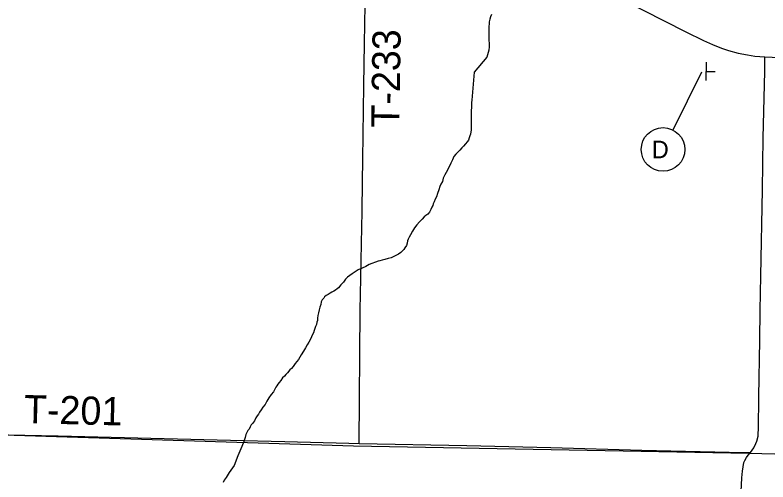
# Model space of a CAD drawing. Extents: x 1 to 1971, y -2 to 1107.
# Drawn here: x 1657.44 to 1664.12, y 1091.98 to 1096.12 of the extents above; entities that cross this region are included whole.
import ezdxf

# ---------------------------------------------------------------- set-up
doc = ezdxf.new("R2010")
doc.units = 0
for name, color, linetype in [('GM_X_County_Road', 7, 'Continuous'), ('GM_X_Minor_River', 7, 'Continuous'), ('GM_X_State_Route', 7, 'Continuous'), ('GM_X_Township', 7, 'Continuous'), ('GM_X_Township_Road', 7, 'Continuous'), ('GM_X_Township_Road_Text', 7, 'Continuous'), ('SH_Text', 7, 'Continuous'), ('SN_P_Signs', 7, 'Continuous')]:
    doc.layers.add(name, color=color, linetype=linetype)

msp = doc.modelspace()

# ---------------------------------------------------------------- linework, layer by layer
at = {"layer": 'GM_X_County_Road'}
for points in [[(1663.9663, 1092.2384), (1663.9964, 1092.279), (1664.0163, 1092.3184), (1664.0244, 1092.3391), (1664.0345, 1092.3822), (1664.037, 1092.4043), (1664.0399, 1092.4484), (1664.0401, 1092.7334), (1664.0507, 1093.2364), (1664.0534, 1093.499), (1664.0583, 1093.8051), (1664.0729, 1094.5707), (1664.0814, 1095.0301), (1664.0961, 1095.6206), (1664.0956, 1095.7086), (1664.0954, 1095.7491)], [(1663.9663, 1092.2384), (1663.9964, 1092.279), (1664.0163, 1092.3184), (1664.0244, 1092.3391), (1664.0345, 1092.3822), (1664.037, 1092.4043), (1664.0399, 1092.4484), (1664.0401, 1092.7334), (1664.0507, 1093.2364), (1664.0534, 1093.499), (1664.0583, 1093.8051), (1664.0729, 1094.5707), (1664.0814, 1095.0301), (1664.0961, 1095.6206), (1664.0956, 1095.7086), (1664.0954, 1095.7491)], [(1663.7714, 1088.7638), (1663.7757, 1088.9203), (1663.7916, 1089.4012), (1663.8088, 1089.904), (1663.8208, 1090.2091), (1663.8384, 1090.5818), (1663.8499, 1090.9095), (1663.8728, 1091.5685), (1663.885, 1091.8932), (1663.8919, 1092.014), (1663.8966, 1092.0716), (1663.9012, 1092.1103), (1663.9093, 1092.1486), (1663.9186, 1092.1687), (1663.9325, 1092.1954), (1663.9457, 1092.2144), (1663.9663, 1092.2384)], [(1663.7714, 1088.7638), (1663.7757, 1088.9203), (1663.7916, 1089.4012), (1663.8088, 1089.904), (1663.8208, 1090.2091), (1663.8384, 1090.5818), (1663.8499, 1090.9095), (1663.8728, 1091.5685), (1663.885, 1091.8932), (1663.8919, 1092.014), (1663.8966, 1092.0716), (1663.9012, 1092.1103), (1663.9093, 1092.1486), (1663.9186, 1092.1687), (1663.9325, 1092.1954), (1663.9457, 1092.2144), (1663.9663, 1092.2384)]]:
    msp.add_lwpolyline(points, dxfattribs=at)
at = {"layer": 'GM_X_Minor_River'}
for points in [[(1661.666, 1096.1256), (1661.6577, 1096.1043), (1661.652, 1096.083), (1661.6464, 1096.0616), (1661.6461, 1096.0402), (1661.6432, 1096.0215), (1661.6429, 1096.0001), (1661.6426, 1095.9759), (1661.6423, 1095.9518), (1661.6448, 1095.9304), (1661.6444, 1095.9009), (1661.6466, 1095.8661), (1661.6463, 1095.8393), (1661.6432, 1095.8099), (1661.6376, 1095.7885), (1661.6319, 1095.7671), (1661.6263, 1095.7458), (1661.5131, 1095.613)], [(1661.5131, 1095.613), (1661.4928, 1095.3669), (1661.4901, 1095.3455), (1661.49, 1095.3241), (1661.49, 1095.3027), (1661.4872, 1095.2706), (1661.4872, 1095.2465), (1661.4871, 1095.2144), (1661.487, 1095.1876), (1661.487, 1095.1635), (1661.4869, 1095.1421), (1661.4869, 1095.1207), (1661.4869, 1095.0993), (1661.4841, 1095.0833), (1661.4814, 1095.0646), (1661.476, 1095.0485), (1661.4706, 1095.0298), (1661.4626, 1095.0111), (1661.4518, 1094.9951), (1661.4357, 1094.9791), (1661.4196, 1094.9577), (1661.4035, 1094.9417), (1661.3848, 1094.9231), (1661.366, 1094.9017), (1661.3499, 1094.8857), (1661.3338, 1094.8644), (1661.3203, 1094.835), (1661.3069, 1094.8056), (1661.2961, 1094.7842), (1661.2639, 1094.7228), (1661.2531, 1094.7041), (1661.2397, 1094.6747), (1661.2316, 1094.6426), (1661.2182, 1094.6213), (1661.2101, 1094.5999), (1661.1993, 1094.5705), (1661.1885, 1094.5384), (1661.1778, 1094.509), (1661.167, 1094.4877), (1661.1589, 1094.4636), (1661.1482, 1094.4449), (1661.1455, 1094.4315), (1661.1374, 1094.4155), (1661.1293, 1094.3941), (1661.1159, 1094.3728), (1661.1025, 1094.3541), (1661.0837, 1094.3408), (1661.0703, 1094.3301), (1661.0516, 1094.3088), (1661.0274, 1094.2848), (1661.0033, 1094.2581), (1660.9845, 1094.2314), (1660.9657, 1094.202), (1660.9496, 1094.17), (1660.9361, 1094.1486), (1660.9281, 1094.1326), (1660.9227, 1094.1166), (1660.92, 1094.0978), (1660.9119, 1094.0765), (1660.8985, 1094.0551), (1660.8877, 1094.0391), (1660.8636, 1094.0124), (1660.8421, 1093.9991), (1660.8234, 1093.9884), (1660.7993, 1093.9778), (1660.7752, 1093.9672), (1660.7484, 1093.9593), (1660.7216, 1093.9513), (1660.6975, 1093.946), (1660.6761, 1093.9407), (1660.66, 1093.9355), (1660.5797, 1093.9063), (1660.5502, 1093.8903), (1660.5181, 1093.8744), (1660.4833, 1093.8584), (1660.4565, 1093.8425), (1660.4297, 1093.8238), (1660.4082, 1093.8105), (1660.3895, 1093.7945), (1660.3707, 1093.7759), (1660.3519, 1093.7492), (1660.3304, 1093.7251), (1660.309, 1093.7011), (1660.2956, 1093.6905), (1660.2822, 1093.6798), (1660.2661, 1093.6692), (1660.25, 1093.6612), (1660.2339, 1093.6532), (1660.2179, 1093.6399), (1660.1991, 1093.6319), (1660.1857, 1093.6213), (1660.1777, 1093.6079), (1660.1642, 1093.5946), (1660.1562, 1093.5759), (1660.1508, 1093.5518), (1660.1427, 1093.5278)], [(1660.1427, 1093.5278), (1660.1373, 1093.5037), (1660.1319, 1093.477), (1660.1265, 1093.4529), (1660.1237, 1093.4315), (1660.121, 1093.4101), (1660.1156, 1093.3941), (1660.1129, 1093.3753), (1660.1048, 1093.3566), (1660.0994, 1093.3379), (1660.094, 1093.3219), (1660.086, 1093.3005), (1660.0752, 1093.2791), (1660.0618, 1093.2498), (1660.0456, 1093.2177), (1660.0295, 1093.1937), (1660.0161, 1093.167), (1659.9973, 1093.1376), (1659.9785, 1093.1055), (1659.9543, 1093.0628), (1659.9248, 1093.0281), (1659.906, 1093.0014), (1659.8899, 1092.9828), (1659.8765, 1092.9721), (1659.855, 1092.9454), (1659.8416, 1092.9294), (1659.8282, 1092.9161), (1659.8121, 1092.9001), (1659.796, 1092.8787), (1659.7826, 1092.86), (1659.7692, 1092.844), (1659.7611, 1092.8307), (1659.7531, 1092.8173), (1659.7423, 1092.8013), (1659.7316, 1092.7773), (1659.7101, 1092.7532), (1659.6913, 1092.7239), (1659.6725, 1092.6945), (1659.6564, 1092.6651), (1659.6376, 1092.6411), (1659.6215, 1092.6171), (1659.6081, 1092.5957), (1659.5973, 1092.5797), (1659.5866, 1092.5637), (1659.5758, 1092.545), (1659.5624, 1092.5209), (1659.5436, 1092.4969), (1659.5329, 1092.4836), (1659.5248, 1092.4676), (1659.5141, 1092.4462), (1659.5033, 1092.4328), (1659.4953, 1092.4168), (1659.4872, 1092.3981), (1659.4791, 1092.3714), (1659.4656, 1092.3286), (1659.4414, 1092.2698), (1659.4145, 1092.2084), (1659.3822, 1092.1229), (1659.3366, 1092.0615), (1659.3124, 1092.0161), (1659.2936, 1091.9921), (1659.2855, 1091.9707)]]:
    msp.add_lwpolyline(points, dxfattribs=at)
at = {"layer": 'GM_X_State_Route'}
msp.add_lwpolyline([(1662.8274, 1096.2607), (1663.3928, 1095.972), (1663.5499, 1095.8949), (1663.6295, 1095.859), (1663.7106, 1095.8271), (1663.7726, 1095.8067), (1663.8567, 1095.7839), (1663.9422, 1095.767), (1664.0068, 1095.7573), (1664.0954, 1095.7491), (1664.3558, 1095.737)], dxfattribs=at)
at = {"layer": 'GM_X_Township'}
msp.add_lwpolyline([(1653.1763, 1092.4976), (1656.8592, 1092.4086), (1656.9549, 1092.4071), (1660.4424, 1092.2976), (1663.9517, 1092.2334), (1668.658, 1092.1116), (1671.0761, 1092.0354), (1672.2022, 1091.993)], dxfattribs=at)
at = {"layer": 'GM_X_Township_Road'}
for points in [[(1660.4916, 1092.3184), (1660.5024, 1093.5021), (1660.5078, 1093.787), (1660.5129, 1094.0937), (1660.5178, 1094.3786), (1660.5219, 1094.6414), (1660.5262, 1094.8383), (1660.5346, 1095.4947), (1660.5405, 1095.8685), (1660.5465, 1096.2115), (1660.5501, 1096.5938), (1660.5584, 1097.1408), (1660.5632, 1097.4654), (1660.5692, 1097.9522), (1660.5764, 1098.3001), (1660.5763, 1098.4243), (1660.58, 1098.4562), (1660.5825, 1098.4759), (1660.5954, 1098.5194)], [(1660.4916, 1092.3184), (1660.5024, 1093.5021), (1660.5078, 1093.787), (1660.5129, 1094.0937), (1660.5178, 1094.3786), (1660.5219, 1094.6414), (1660.5262, 1094.8383), (1660.5346, 1095.4947), (1660.5405, 1095.8685), (1660.5465, 1096.2115), (1660.5501, 1096.5938), (1660.5584, 1097.1408), (1660.5632, 1097.4654), (1660.5692, 1097.9522), (1660.5764, 1098.3001), (1660.5763, 1098.4243), (1660.58, 1098.4562), (1660.5825, 1098.4759), (1660.5954, 1098.5194)], [(1656.9539, 1092.4077), (1657.2287, 1092.3994), (1657.8192, 1092.386), (1659.35, 1092.3476), (1659.8311, 1092.3358), (1660.3997, 1092.32), (1660.4916, 1092.3184)], [(1656.9539, 1092.4077), (1657.2287, 1092.3994), (1657.8192, 1092.386), (1659.35, 1092.3476), (1659.8311, 1092.3358), (1660.3997, 1092.32), (1660.4916, 1092.3184)], [(1660.4916, 1092.3184), (1661.4495, 1092.3007), (1662.193, 1092.2817), (1663.0022, 1092.2599), (1663.907, 1092.2397), (1663.9663, 1092.2384)], [(1660.4916, 1092.3184), (1661.4495, 1092.3007), (1662.193, 1092.2817), (1663.0022, 1092.2599), (1663.907, 1092.2397), (1663.9663, 1092.2384)]]:
    msp.add_lwpolyline(points, dxfattribs=at)
at = {"layer": 'SH_Text'}
msp.add_line((1663.5316, 1095.6145), (1663.2784, 1095.1006), dxfattribs=at)
for points in [[(1662.8274, 1096.2607), (1663.3928, 1095.972), (1663.5499, 1095.8949), (1663.6295, 1095.859), (1663.7106, 1095.8271), (1663.7726, 1095.8067), (1663.8567, 1095.7839), (1663.9422, 1095.767), (1664.0068, 1095.7573), (1664.0954, 1095.7491)], [(1662.8274, 1096.2607), (1663.3928, 1095.972), (1663.5499, 1095.8949), (1663.6295, 1095.859), (1663.7106, 1095.8271), (1663.7726, 1095.8067), (1663.8567, 1095.7839), (1663.9422, 1095.767), (1664.0068, 1095.7573), (1664.0954, 1095.7491), (1664.3558, 1095.737)]]:
    msp.add_lwpolyline(points, dxfattribs=at)
msp.add_circle((1663.1908, 1094.9279), 0.1936, dxfattribs=at)
at = {"layer": 'SN_P_Signs'}
for p, q in [((1663.5752, 1095.7014), (1663.5705, 1095.5415)), ((1663.5729, 1095.6214), (1663.6528, 1095.619))]:
    msp.add_line(p, q, dxfattribs=at)

# ---------------------------------------------------------------- texts
at = {"layer": 'GM_X_Township_Road_Text'}
for s, rotation, p in [('T-233', 89.16098, (1660.8488, 1095.1198)), ('T-201', 358.59569, (1657.5131, 1092.4993))]:
    msp.add_text(s, height=0.25, rotation=rotation, dxfattribs=at).set_placement(p)
at = {"layer": 'SH_Text'}
msp.add_text('D', height=0.156, dxfattribs=at).set_placement((1663.0911, 1094.8499))

doc.saveas('drawing.dxf')
